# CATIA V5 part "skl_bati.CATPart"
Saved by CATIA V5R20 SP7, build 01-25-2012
Part number: skl_bati
Publications: "axe_pivot_0_3", "axe_pivot_0_1", "axe_pivot_0_5", "PlanRef", "PointG", "PointA", "PointD"
Bounding box of the stored display mesh (mm): x 0 to 20, y -214 to 300, z 0 to 129.244
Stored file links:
  U:\Projet IAO\omeyer\Catia\skl_bati.CATPart
  U:\Projet IAO\omeyer\Catia\skl_748.CATProduct
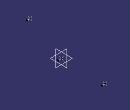
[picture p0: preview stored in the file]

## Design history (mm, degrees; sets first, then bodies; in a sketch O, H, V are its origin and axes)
Set1
  Plane1 "PlanRef": linked copy from another document
  DatumPoint1 "PointG": linked copy from another document
  Point1 "PointA": linked copy from another document
  Point2 "PointD": linked copy from another document
Set2
  Line1 "axe_pivot_0_5": type Normal, RefPoint DatumPoint1, RefSkin Plane1, Start 0, End 20
  Line2 "axe_pivot_0_1": type Normal, RefPoint Point1, RefSkin Plane1, Start 0, End 20
  Line3 "axe_pivot_0_3": type Normal, RefPoint Point2, RefSkin Plane1, Start 0, End 20
Body1 (main body)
